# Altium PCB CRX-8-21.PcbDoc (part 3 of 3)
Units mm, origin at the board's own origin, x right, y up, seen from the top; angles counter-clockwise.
Board outline 160.02 x 101.6 mm, 2 copper layers (TopLayer, BottomLayer), stack 1.535 mm thick; 254 components, 127 nets, 595 pads, 4322 vias.
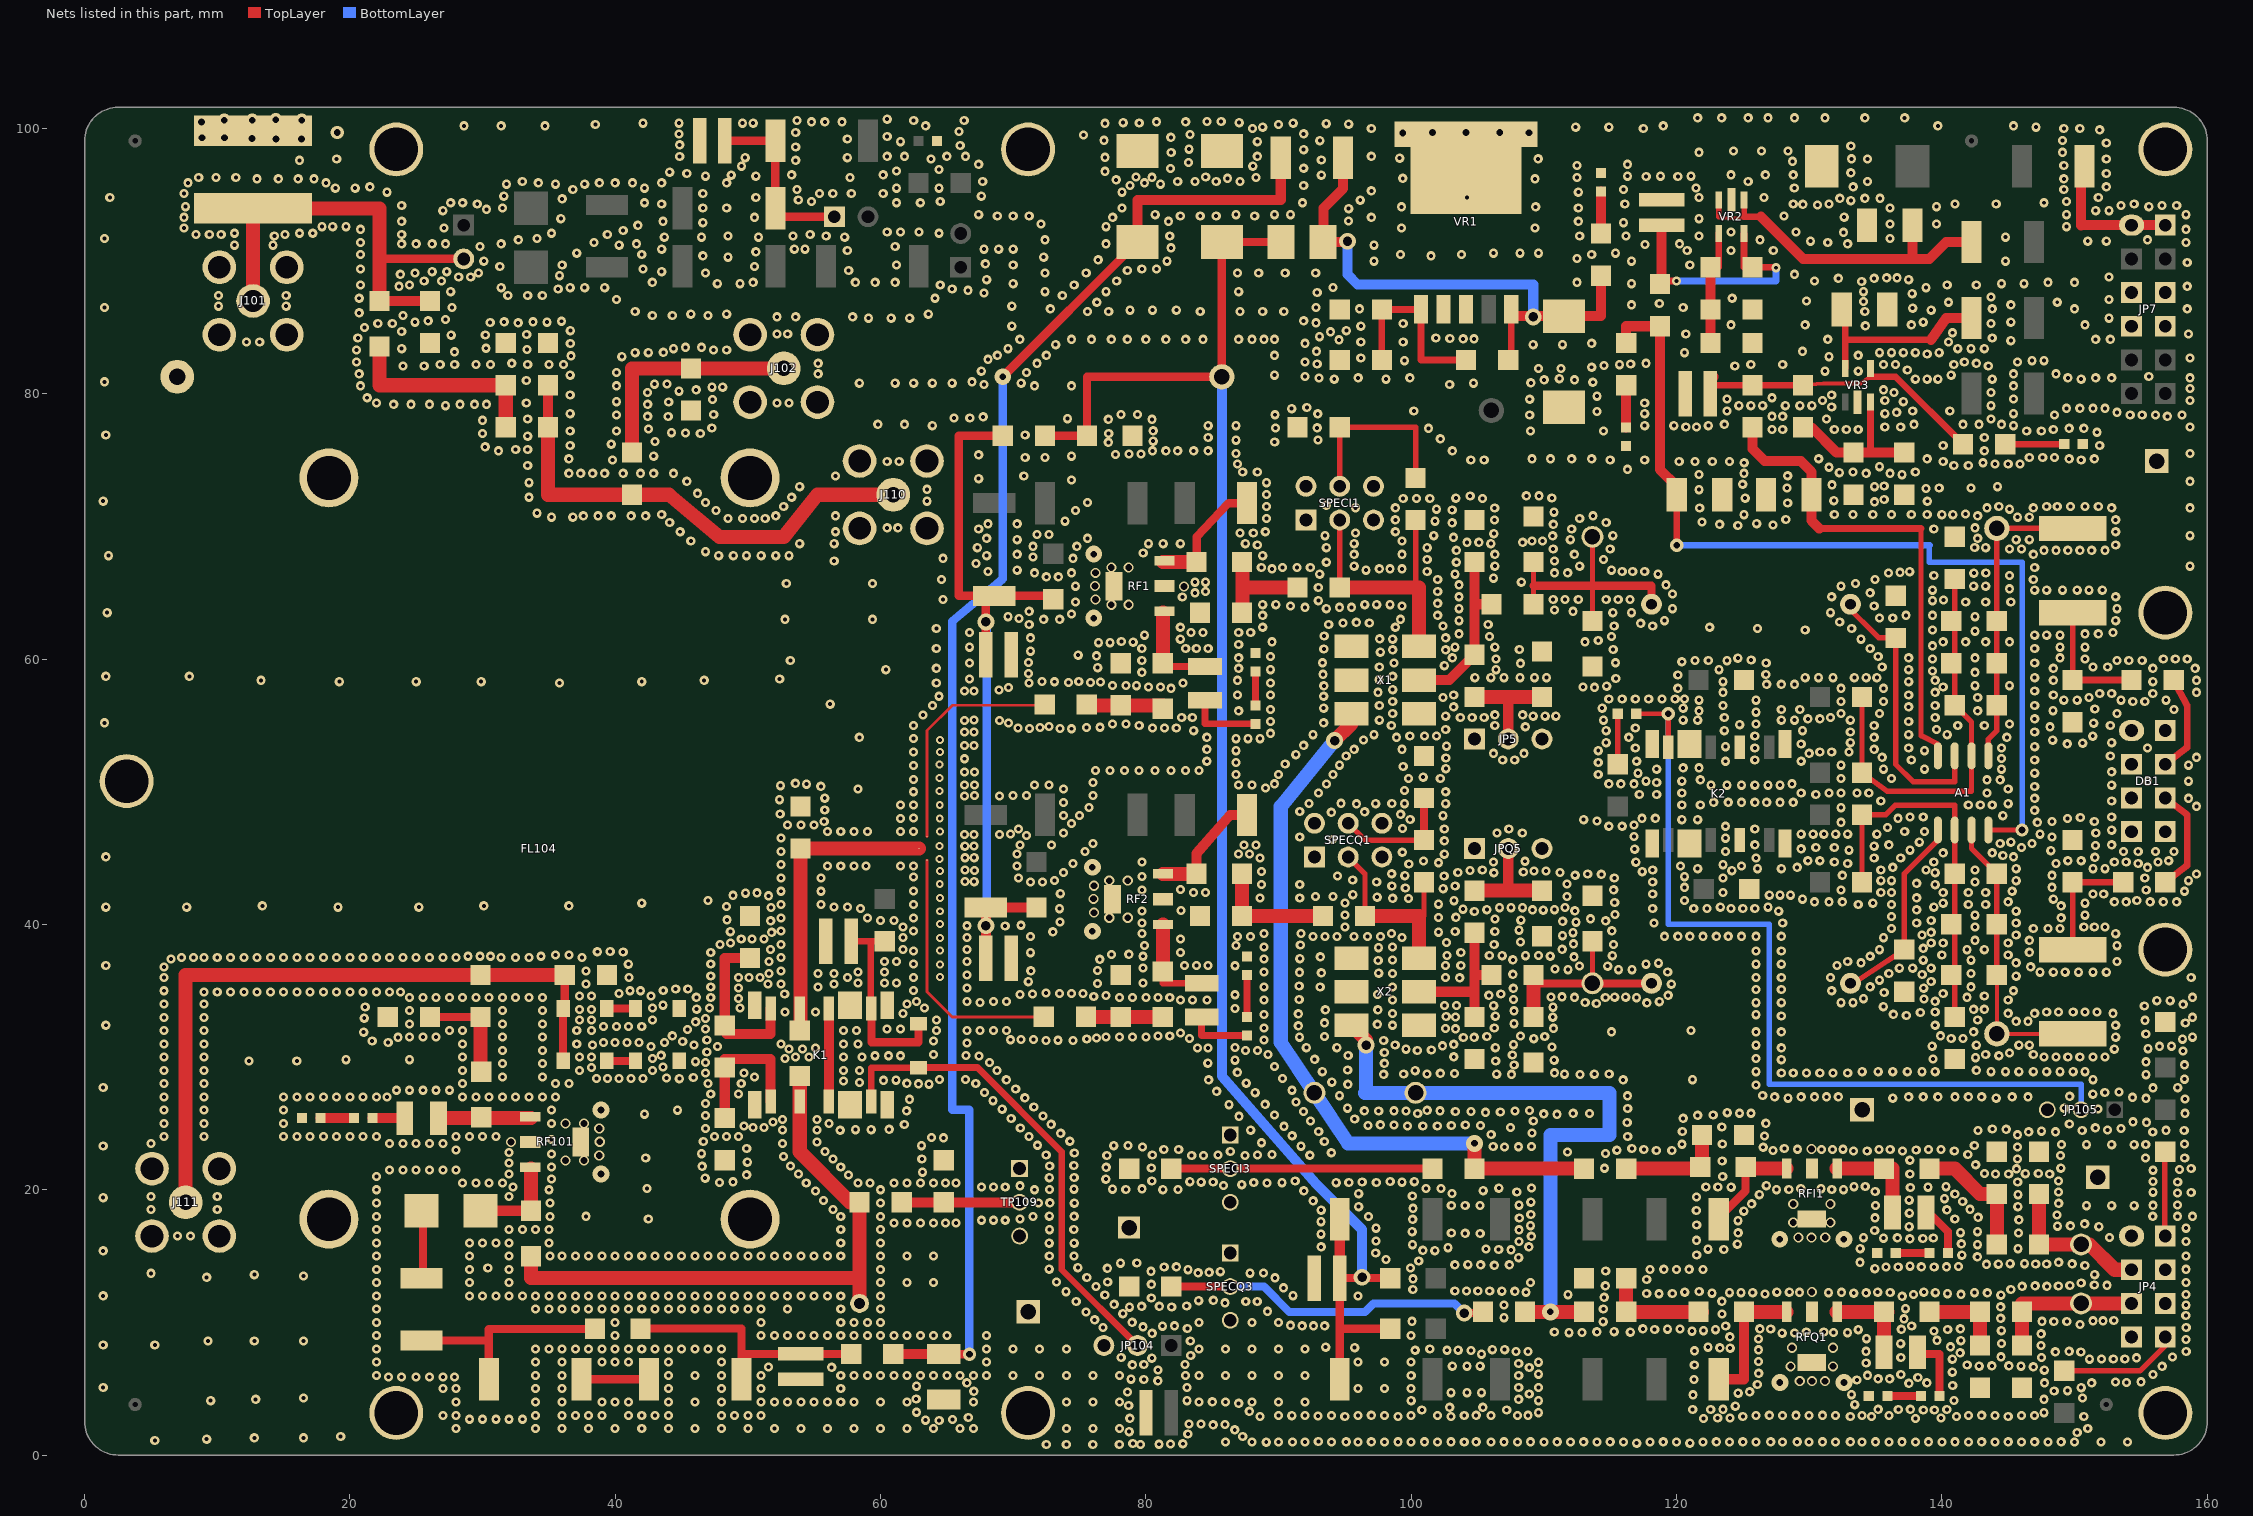
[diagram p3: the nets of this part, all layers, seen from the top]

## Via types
v1: diameter 0.7, hole 0.3, TopLayer to BottomLayer, 3209 vias
v2: diameter 0.68, hole 0.3, TopLayer to BottomLayer, 1006 vias
v3: diameter 0.762, hole 0.508, TopLayer to BottomLayer, 39 vias
v4: diameter 1, hole 0.508, TopLayer to BottomLayer, 20 vias
v5: diameter 1.27, hole 0.508, TopLayer to BottomLayer, 19 vias
v6: diameter 0.6, hole 0.3, TopLayer to BottomLayer, 19 vias
v7: diameter 1.27, hole 0.711, TopLayer to BottomLayer, 10 vias

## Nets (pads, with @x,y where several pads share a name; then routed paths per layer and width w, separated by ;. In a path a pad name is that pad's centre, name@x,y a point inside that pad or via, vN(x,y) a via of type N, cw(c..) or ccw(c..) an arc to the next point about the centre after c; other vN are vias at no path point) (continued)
GND: (continued)
  other v6: 64.489,36.035 64.486,36.996 64.489,38.048 64.489,38.992 64.486,40.034 64.476,40.993 64.466,41.998 64.463,43.038 64.466,44.037 64.461,44.937 64.458,45.895 64.471,47 64.463,47.986 64.463,49.01 64.458,50.044 64.461,51.03 64.461,52.042 64.474,53.007 64.468,53.895
K2-RELAY: JP105.2 K2.8 LED4.2 | length 66
  TopLayer w0.305: LED4.2@116.84,55.88 LED4.2@116.967,55.88 v4(119.38,55.88)
  TopLayer w0.406: K2.8@119.38,53.34 K2.8@119.38,53.355 v4(119.38,55.88)
  BottomLayer w0.406: v4(119.38,55.88) 119.38,40.005 127,40.005 127,27.94 150.495,27.94 JP105.2@150.495,26.035
LF4: C40.1 JP5.2 R40.2 | length 8.3
  TopLayer w0.762: JP5.2@107.315,53.975 107.315,57.15
  TopLayer w1.064: R40.2@104.775,57.15 107.315,57.15 C40.1@109.855,57.15
LFI1: R20.1 R21.1 R40.1 X1.2 | length 13.2
  TopLayer w0.762: X1.2@100.584,58.42 102.87,58.42 R40.1@104.775,60.325 104.775,64.135 ; R20.1@104.775,67.31 104.775,64.135 ; R21.1@106.045,64.135 104.775,64.135
LFI2: C20.1 C21.1 C22.1 R21.2 TP14.TP | length 19.8
  TopLayer w0.406: R21.2@109.22,64.135 109.22,65.532 C20.1@109.22,67.31 ; C21.1@113.665,62.865 113.665,65.532 TP14.TP@113.665,69.215
  TopLayer w0.61: 109.22,65.532 113.665,65.532 118.11,65.532 C22.1@118.11,64.135
LFI3: A1.3 C22.2 R22.1 | length 21.4
  TopLayer w0.406: C22.2@132.715,64.135 135.255,61.595 R22.1@136.525,61.595 136.525,52.07 137.836,50.759 140.97,50.759 A1.3@140.97,52.705 A1.3@140.97,52.832
LFQ1: RQ20.1 RQ21.1 RQ40.1 X2.2 | length 11.8
  TopLayer w0.762: X2.2@100.584,34.925 104.775,34.925 ; RQ20.1@104.775,33.02 104.775,34.925 ; RQ40.1@104.775,39.37 104.775,36.195 ; RQ21.1@106.045,36.195 104.775,36.195 ; 104.775,34.925 104.775,36.195
LFQ2: CQ20.1 CQ21.1 CQ22.1 RQ21.2 TPQ14.TP | length 15.2
  TopLayer w0.406: TPQ14.TP@113.665,35.56 CQ21.1@113.665,38.735
  TopLayer w0.61: RQ21.2@109.22,35.56 TPQ14.TP@113.665,35.56 CQ22.1@118.11,35.56
  TopLayer w1.064: CQ20.1@109.22,33.02 109.22,35.56 RQ21.2@109.22,36.195
LFQ3: A1.5 CQ22.2 RQ22.1 | length 14.5
  TopLayer w0.406: CQ22.2@133.35,35.56 RQ22.1@137.16,38.1 137.16,43.815 139.7,46.355 A1.5@139.7,46.99
LFQ4: CQ40.1 JPQ5.2 RQ40.2 | length 7.6
  TopLayer w0.762: 107.315,42.545 JPQ5.2@107.315,45.72
  TopLayer w1.064: RQ40.2@104.775,42.545 107.315,42.545 CQ40.1@109.22,42.545
LNA1: C100.1 GAP1.1 J101.1 JP102.2 R110.1 | length 33.7
  TopLayer w0.635: 22.225,90.17 JP102.2@28.575,90.17
  TopLayer w0.762: C100.1@22.225,86.995 R110.1@26.035,86.995
  TopLayer w1.064: J101.1@12.7,86.995 GAP1.1@12.7,93.98 22.225,93.98 22.225,90.17 C100.1@22.225,86.995
LNA2: C100.2 R101.1 R103.1 | length 15.6
  TopLayer w1.064: C100.2@22.225,83.566 22.225,80.645 R101.1@31.75,80.645 R103.1@31.75,77.47
LNA3: J110.1 R102.2 R103.2 R210.2 | length 37
  TopLayer w0.762: R103.2@34.925,77.47 R102.2@34.925,80.645
  TopLayer w1.064: R103.2@34.925,77.47 34.925,72.39 R210.2@41.275,72.39 44.052,72.39 47.862,69.215 52.705,69.215 55.245,72.39 J110.1@60.96,72.39
LNA4: D101.CATH D103.ANOD J111.1 R104.1 R105.1 | length 52.2
  TopLayer w0.61: D103.ANOD@36.068,29.591 D103.ANOD@36.068,29.718 D101.CATH@36.068,33.655 ; D101.CATH@36.195,33.782 R104.1@36.195,36.195
  TopLayer w1.064: J111.1@7.62,19.05 7.62,36.195 R105.1@29.845,36.195 R104.1@36.195,36.195
LNA5: C101.1 R105.2 R106.1 | length 7.6
  TopLayer w0.635: R106.1@26.035,33.02 R105.2@29.845,33.02
  TopLayer w1.064: C101.1@29.845,29.21 R105.2@29.845,33.02
LNA6: C101.2 L50.2 RF101.1 | length 7
  TopLayer w1.064: L50.2@26.67,25.4 RF101.1@33.655,25.4
LNA7: C102.1 L104.1 RF101.3 | length 7
  TopLayer w0.762: L104.1@29.845,18.415 C102.1@33.655,18.415
  TopLayer w1.064: C102.1@33.655,18.415 RF101.3@33.655,21.59
LNA8: C102.2 K1.6 R111.1 R208.1 TP108.TP | length 47
  TopLayer w1.064: C102.2@33.655,14.9 33.655,13.335 58.42,13.335 ; R208.1@53.909,28.575 53.909,26.035 K1.6@53.909,26.655 53.909,22.86 57.719,19.05 R111.1@58.42,19.05 58.42,13.335 ; TP108.TP@58.42,11.43 58.42,13.335
LNA9: K1.5 R204.1 R205.1 | length 11.1
  TopLayer w0.762: R204.1@48.26,25.4 R205.1@48.26,29.21 48.26,29.845 51.709,29.845 K1.5@51.709,26.655
LNA10: K1.4 R205.2 R206.1 | length 13.1
  TopLayer w0.762: R205.2@48.26,32.131 R205.2@48.26,32.385 ; R206.1@50.165,37.465 48.26,37.465 R205.2@48.26,32.385 ; K1.4@51.714,33.655 51.709,31.75 48.387,31.75 R205.2@48.26,32.385
LNA11: K1.2 K1.7 | length 7
  TopLayer w0.762: K1.7@56.109,26.655 K1.2@56.109,33.64
LNA13: R111.2 R112.1 TP109.2 | length 8.9
  TopLayer w0.762: R111.2@61.595,19.05 R112.1@64.77,19.05 TP109.2@70.485,19.05
LOI1: JP4.3 R10.2 R11.1 TP2.TP | length 11.6
  TopLayer w1.064: R10.2@147.32,19.685 R11.1@147.32,15.875 TP2.TP@150.495,15.875 151.13,15.875 153.035,13.97 JP4.3@154.305,13.97
LOI2: C4.1 R11.2 R12.2 | length 9.7
  TopLayer w1.064: C4.1@139.065,21.59 140.97,21.59 142.875,19.685 R12.2@144.145,19.685 R11.2@144.145,15.875
LOI3: C4.2 L53.1 RFI1.1 | length 7.5
  TopLayer w1.064: RFI1.1@132.08,21.59 C4.2@135.636,21.59 136.271,21.59 L53.1@136.271,18.288
LOI4: C5.2 L3.1 RFI1.3 | length 7.7
  TopLayer w0.61: L3.1@123.19,17.78 123.19,17.907 125.2,19.917 C5.2@125.2,21.59
  TopLayer w1.064: C5.2@125.2,21.59 RFI1.3@128.27,21.59
LOI5: C5.1 R16.1 R17.1 | length 8.3
  TopLayer w1.064: R16.1@116.205,21.59 121.92,21.59 R17.1@121.92,24.13
LOI6: R16.2 R18.1 TP5.TP X1.6 | length 55.6
  TopLayer w1.064: v7(94.23,53.857) 95.504,55.131 X1.6@95.504,55.88 ; v5(104.775,23.495) R18.1@104.775,21.59 R16.2@113.03,21.59
  BottomLayer w1.064: v7(94.23,53.857) 90.17,48.895 90.17,31.115 TP5.TP@92.71,27.305 95.25,23.495 v5(104.775,23.495)
LOQ1: JP4.5 RQ10.2 RQ11.1 TP1.TP | length 11.4
  TopLayer w1.064: RQ10.2@146.05,8.255 RQ11.1@146.05,10.795 146.05,11.43 TP1.TP@150.495,11.43 JP4.5@154.305,11.43
LOQ2: CQ4.1 RQ11.2 RQ12.2 | length 6.3
  TopLayer w1.064: CQ4.1@139.065,10.795 RQ11.2@142.875,10.795 RQ12.2@142.875,8.255
LOQ3: CQ4.2 L54.1 RFQ1.1 | length 6.9
  TopLayer w1.064: RFQ1.1@132.08,10.795 CQ4.2@135.636,10.795 ; L54.1@135.636,7.747 CQ4.2@135.636,10.795 ; CQ4.2@135.89,10.795 CQ4.2@135.636,10.795
LOQ4: CQ5.1 LQ3.1 RFQ1.3 | length 10.2
  TopLayer w0.762: LQ3.1@123.19,5.715 125.095,5.715 CQ5.1@125.095,10.795
  TopLayer w1.064: CQ5.1@125.095,10.795 RFQ1.3@128.27,10.795
LOQ5: CQ5.2 RQ16.1 RQ17.1 | length 8.3
  TopLayer w1.064: RQ17.1@116.205,13.335 RQ16.1@116.205,10.795 CQ5.2@121.666,10.795 CQ5.2@121.92,10.795
LOQ6: RQ16.2 RQ18.1 TPQ5.TP X2.6 | length 49.4
  TopLayer w1.064: X2.6@95.504,32.385 96.6,31.289 v7(96.6,30.9) ; RQ18.1@108.585,10.795 v5(110.49,10.795) RQ16.2@113.03,10.795
  BottomLayer w1.064: v7(96.6,30.9) 96.6,27.385 96.52,27.305 TPQ5.TP@100.33,27.305 114.935,27.305 114.935,24.13 110.49,24.13 v5(110.49,10.795)
MMIC_BUS: JP7.1 JP7.2 L1.2 | length 10.8
  TopLayer w0.762: L1.2@150.5,97.145 150.5,92.7 154.305,92.708 155.3,92.71 JP7.2@156.845,92.71
N43121: A1.6 CQ25.2 CQ26.2 RQ25.2 RQ26.1 RQ27.1 RQ28.1 | length 28.3
  TopLayer w0.406: RQ28.1@133.985,43.18 RQ27.1@133.985,48.26 135.763,48.26 136.48,48.977 140.97,48.977 A1.6@140.97,47.117 RQ25.2@140.97,43.815 RQ26.1@140.97,33.02
N78610: R30.2 R31.1 R32.1 VR1.1 | length 14.2
  TopLayer w0.508: R32.1@97.79,82.55 R31.1@97.79,86.36 VR1.1@100.736,86.36 ; VR1.1@100.965,86.36 VR1.1@100.736,86.36 ; R30.2@104.14,82.55 100.736,82.55 VR1.1@100.736,86.36
N571744: A1.2 C25.2 C26.2 R25.2 R26.1 R27.1 R28.1 | length 31
  TopLayer w0.406: R28.1@133.985,57.15 R27.1@133.985,51.435 135.89,50.038 142.24,50.038 A1.2@142.24,52.705 142.24,55.245 R25.2@140.97,56.515 R26.1@140.97,66.04
N3983590: LED1.1 R53.2 | length 3.2
  TopLayer w0.762: R53.2@114.3,92.075 LED1.1@114.3,95.25
N11845427: J102.1 R209.1 R210.1 | length 17.8
  TopLayer w0.61: R209.1@45.72,81.915 R209.1@45.815,81.915
  TopLayer w1.064: R210.1@41.275,75.565 41.275,81.915 R209.1@45.72,81.915 ; R209.1@45.8,81.9 45.815,81.915 J102.1@52.705,81.915
N11893488: JP4.2 L10.1 | length 6.3
  TopLayer w0.406: JP4.2@156.8,16.55 L10.1@156.8,22.9
N11893519: JP4.8 L107.1 | length 9
  TopLayer w0.406: L107.1@149.225,6.35 154.94,6.35 156.845,8.255 JP4.8@156.845,8.89
N114271571: D103.CATH D104.ANOD | length 2
  TopLayer w0.61: D103.CATH@39.37,29.718 D104.ANOD@41.402,29.718
N114277610: D101.ANOD D102.CATH | length 2.2
  TopLayer w0.61: D101.ANOD@39.37,33.655 D102.CATH@41.529,33.655
N117251600: C53.1 R73.1 | length 2.5
  TopLayer w0.61: C53.1@136.525,15.24 R73.1@139.065,15.24
N117251601: L53.2 R73.2 | length 3.8
  TopLayer w0.61: L53.2@138.811,18.288 139.414,17.886 140.462,16.838 R73.2@140.462,15.24
N117251820: C51.1 R71.1 | length 2.5
  TopLayer w0.508: R71.1@88.265,56.515 C51.1@88.265,59.055
N117251821: L51.1 R71.2 | length 5.6
  TopLayer w0.508: L51.1@84.455,56.896 84.455,55.118 R71.2@88.265,55.118
N117252040: C52.1 R72.1 | length 3
  TopLayer w0.508: R72.1@87.63,33.02 C52.1@87.63,36.068
N117252041: L52.1 R72.2 | length 4.8
  TopLayer w0.508: L52.1@84.201,33.02 84.201,31.623 R72.2@87.63,31.623
N117252260: C54.1 R74.1 | length 2.5
  TopLayer w0.61: C54.1@135.89,4.445 R74.1@138.43,4.445
N117252261: L54.2 R74.2 | length 4.6
  TopLayer w0.61: L54.2@138.43,7.62 139.827,7.62 R74.2@139.827,4.445
N117311520: C50.1 R70.1 | length 2.5
  TopLayer w0.762: C50.1@17.78,25.4 R70.1@20.32,25.4
N117311521: L50.1 R70.2 | length 2.4
  TopLayer w0.762: R70.2@21.717,25.4 L50.1@24.13,25.4
N119030500: LED4.1 R54.1 | length 3.8
  TopLayer w0.406: R54.1@115.57,52.07 LED4.1@115.57,55.88
OUTI1: A1.1 C25.1 C26.1 C27.1 R25.1 TP3.TP | length 23.1
  TopLayer w0.406: A1.1@143.51,52.705 143.51,53.975 144.145,54.61 R25.1@144.145,56.515 C25.1@144.145,59.69 C26.1@144.145,62.865 TP3.TP@144.145,69.85 C27.1@149.86,69.85
OUTI2: C27.2 R29.1 R50.1 | length 9.5
  TopLayer w0.406: R29.1@149.86,58.42 C27.2@149.86,63.5
  TopLayer w0.508: R29.1@149.86,58.42 R50.1@154.305,58.42
OUTI3: DB1.4 R50.2 | length 7.4
  TopLayer w0.508: DB1.4@156.845,52.07 158.496,53.34 158.496,56.515 R50.2@157.48,58.42
OUTQ1: A1.7 CQ25.1 CQ26.1 CQ27.1 RQ25.1 TPQ3.TP | length 21.9
  TopLayer w0.305: CQ26.1@144.145,36.195 TPQ3.TP@144.145,31.75 CQ27.1@149.86,31.75
  TopLayer w0.406: A1.7@142.24,47.117 142.24,45.72 RQ25.1@144.145,43.815 CQ25.1@144.145,40.005 CQ26.1@144.145,36.195
OUTQ2: CQ27.2 RQ29.1 RQ50.1 | length 8.9
  TopLayer w0.406: CQ27.2@149.86,38.1 RQ29.1@149.86,43.18
  TopLayer w0.508: RQ29.1@149.86,43.18 RQ50.1@153.67,43.18
OUTQ3: DB1.6 RQ50.2 | length 8
  TopLayer w0.508: RQ50.2@156.845,43.18 158.496,44.45 158.496,48.26 DB1.6@156.845,49.53
RELAY1: C108.1 D105.CATH K1.1 R207.2 | length 15.4
  TopLayer w0.508: C108.1@57.785,38.735 59.259,38.735 ; K1.1@59.259,33.655 59.259,38.735 ; R207.2@60.325,38.735 60.325,38.5 60.09,38.735 59.259,38.735
  TopLayer w0.61: K1.1@59.309,33.655 59.309,31.115 62.865,31.115 D105.CATH@62.865,32.512
RELAY2: D105.ANOD JP104.2 K1.8 | length 36.5
  TopLayer w0.508: K1.8@59.3,26.645 59.3,29.2 62.855,29.2 D105.ANOD@62.865,29.21 67.31,29.21 73.66,22.86 73.66,13.97 JP104.2@79.375,8.255
RF: ?.2 ?.3 R1.1 R2.1 | length 37.2
  TopLayer w0.2: 63.496,34.929 ?.3@63.496,44.827 ; ?.2@63.496,46.627 63.496,54.606 ; 63.5,34.925 65.405,33.02 R2.1@72.308,33.02 ; 63.5,54.61 65.405,56.515 R1.1@72.433,56.515
RF1: ?.1 K1.3 R7.1 R208.2 | length 22.5
  TopLayer w1.064: R208.2@53.975,32.068 R7.1@53.975,45.72 ; R7.1@54.101,45.718 54.11,45.727 ?.1@62.896,45.727
RFI2: C1.2 R1.2 R3.1 | length 5.5
  TopLayer w1.064: R1.2@75.739,56.515 R3.1@78.105,56.515 C1.2@81.28,56.515
rfi2x: 
RFI3: C1.1 L51.2 RF1.1 | length 7
  TopLayer w0.508: C1.1@81.28,59.436 L51.2@84.455,59.436
  TopLayer w1.064: C1.1@81.28,59.69 RF1.1@81.28,63.5
RFI4: C2.1 L4.1 RF1.3 | length 9.3
  TopLayer w0.635: C2.1@83.82,67.31 83.82,69.215 86.233,71.755 L4.1@87.63,71.755
  TopLayer w1.064: RF1.3@81.28,67.31 C2.1@83.82,67.31
RFI5: C2.2 R60.2 R61.1 | length 8
  TopLayer w1.064: R60.2@87.295,63.5 87.295,65.405 ; C2.2@87.295,67.31 87.295,65.405 ; R61.1@91.44,65.405 87.295,65.405
RFI6: R61.2 R63.2 SPECI1.3 X1.3 | length 20.8
  TopLayer w0.406: R61.2@94.615,65.405 SPECI1.3@94.615,70.485 ; 100.33,65.405 R63.2@100.33,70.485
  TopLayer w1.064: R61.2@94.615,65.405 100.33,65.405 100.584,65.405 X1.3@100.584,60.96 X1.3@100.33,60.96
RFQ2: CQ1.2 R2.2 R4.1 | length 5.7
  TopLayer w0.406: CQ1.2@81.28,33.02 CQ1.2@81.28,33.274
  TopLayer w1.064: R2.2@75.801,33.02 R4.1@78.105,33.02 CQ1.2@81.28,33.02
RFQ3: CQ1.1 L52.2 RF2.1 | length 7.4
  TopLayer w0.508: CQ1.1@81.28,36.195 81.28,35.56 L52.2@84.201,35.56
  TopLayer w1.064: CQ1.1@81.28,36.195 CQ1.1@81.28,36.449 RF2.1@81.28,40.005
RFQ4: CQ2.1 LQ4.1 RF2.3 | length 9.2
  TopLayer w0.762: CQ2.1@83.82,43.815 83.82,45.339 86.36,48.26 LQ4.1@87.63,48.26
  TopLayer w1.064: RF2.3@81.28,43.815 CQ2.1@83.82,43.815
RFQ5: CQ2.2 RQ60.2 RQ61.1 | length 9.3
  TopLayer w1.064: CQ2.2@87.249,43.815 RQ60.2@87.249,40.64 RQ61.1@93.345,40.64
RFQ6: RQ61.2 RQ63.2 SPECQ1.3 X2.3 | length 15.4
  TopLayer w0.406: SPECQ1.3@95.25,45.085 96.52,43.815 RQ61.2@96.52,40.64 ; 100.584,40.64 100.965,40.64 RQ63.2@100.965,43.18
  TopLayer w1.064: RQ61.2@96.52,40.64 100.584,40.64 X2.3@100.584,37.465 X2.3@100.33,37.465
SPEC-I: R63.1 R64.2 SPECI1.4 | length 14
  TopLayer w0.406: SPECI1.4@94.615,73.025 R64.2@94.615,77.47 100.33,77.47 R63.1@100.33,73.66
SPEC-Q: RQ63.1 RQ64.2 SPECQ1.4 | length 9.4
  TopLayer w0.406: SPECQ1.4@95.25,47.625 96.52,46.355 RQ63.1@100.965,46.355
  TopLayer w0.61: RQ63.1@100.965,46.355 RQ64.2@100.965,49.53
TP-I2: R18.2 R19.2 SPECI3.2 | length 19.7
  TopLayer w0.61: R19.2@81.915,21.59 SPECI3.2@86.36,21.59 R18.2@101.6,21.59
TP-Q1: RQ18.2 RQ19.2 SPECQ3.2 | length 24.9
  TopLayer w0.61: RQ19.2@81.915,12.7 SPECQ3.2@86.36,12.7 ; v7(104,10.7) 105.315,10.7 RQ18.2@105.41,10.795
  BottomLayer w0.61: SPECQ3.2@86.36,12.7 88.9,12.7 90.805,10.795 96.52,10.795 97.155,11.43 103.27,11.43 v7(104,10.7)
VC10: C6.1 C7.1 R6.1 R37.1 R92.2 R93.1 RQ6.1 | length 57.5
  TopLayer w0.635: C7.1@67.945,60.325 v7(67.945,62.8) R6.1@67.945,64.77 ; R37.1@69.215,76.835 65.885,76.835 65.885,64.77 R6.1@67.945,64.77 ; R92.2@73.025,64.77 R6.1@68.58,64.77 R6.1@67.945,64.77
  TopLayer w0.762: C6.1@67.945,37.465 v7(67.945,39.9) RQ6.1@67.945,41.275 R93.1@71.755,41.275
  BottomLayer w0.635: v7@68,39.8 v7@68,62.66
VC14: C107.1 JP103.1 R116.1 R120.2 | length 13.6
  TopLayer w0.635: C107.1@48.26,99.06 R116.1@52.07,99.06 R120.2@52.07,93.98 52.705,93.345 JP103.1@56.515,93.345
VCC: C33.1 C34.1 CQ7.1 L2.1 R13.1 R37.2 R91.1 R94.1 RQ13.1 TP9.TP | length 124.1
  TopLayer w0.61: RQ13.1@94.615,5.715 94.615,9.525 CQ7.1@94.615,13.335 R91.1@98.425,13.335
  TopLayer w0.635: R37.2@72.39,76.835 C34.1@75.565,76.835 75.565,81.28 TP9.TP@85.725,81.28 C33.1@85.725,91.44 L2.1@90.17,91.44 ; 94.615,9.525 R94.1@98.425,9.525
  TopLayer w0.762: CQ7.1@94.615,13.335 R13.1@94.615,17.78
  BottomLayer w0.762: TP9.TP@85.725,81.28 85.725,28.575 92.844,20.439 96.3,16.983 v7(96.3,13.4)
VDD: A1.8 C23.1 R23.1 R51.2 | length 70.9
  TopLayer w0.406: A1.8@143.51,47.117 v4(146.05,47.117)
  TopLayer w0.508: v4(120.015,68.58) C23.1@120.015,72.39
  TopLayer w0.762: R51.2@116.205,83.82 116.205,85.09 R23.1@118.745,85.09 118.745,74.295 120.015,73.025 C23.1@120.015,72.39
  BottomLayer w0.406: 139.065,68.58 139.065,67.31 146.05,67.31 v4(146.05,47.117)
  BottomLayer w0.508: v4(120.015,68.58) 139.065,68.58
VEE: A1.4 CQ24.1 RQ24.2 | length 36.9
  TopLayer w0.406: 138.43,69.85 138.43,54.229 139.7,53.594 A1.4@139.7,52.705
  TopLayer w0.508: 130.762,69.85 138.43,69.85
  TopLayer w0.762: RQ24.2@125.73,77.47 125.73,75.852 126.652,74.93 129.363,74.93 130.175,74.118 CQ24.1@130.175,72.39 130.175,70.437 130.762,69.85
VLNA1: C104.1 C105.1 L106.1 R107.1 | length 114
  TopLayer w0.635: C105.1@64.77,7.62 64.79,7.6 v4(66.7,7.6) ; v5(69.215,81.28) C104.1@79.375,91.44
  TopLayer w0.762: R107.1@60.96,7.62 C105.1@64.77,7.62 ; C104.1@79.375,91.44 79.375,94.615 90.17,94.615 L106.1@90.17,97.79
  BottomLayer w0.635: v4(66.7,7.6) 66.675,7.625 66.675,26.035 65.405,26.035 65.405,62.865 69.215,66.04 v5(69.215,81.28)
VLNA2: C106.1 R90.1 R107.2 R108.2 | length 19.7
  TopLayer w0.61: R90.1@41.91,9.525 49.53,9.525 49.53,7.62 ; R108.2@49.53,5.715 49.53,7.62 ; R107.2@57.785,7.62 C106.1@53.975,7.62 49.53,7.62
VLNA3: R108.1 R109.2 | length 5.1
  TopLayer w0.61: R109.2@37.465,5.715 R108.1@42.545,5.715
VLNA4: L103.2 R90.2 R109.1 | length 16.9
  TopLayer w0.61: L103.2@25.4,8.636 30.48,8.636
  TopLayer w0.635: R109.1@30.48,5.715 30.48,8.636 30.48,9.48 30.5,9.5 38.456,9.5 R90.2@38.481,9.525
VLNA5: L103.1 L104.2 | length 5.1
  TopLayer w0.61: L103.1@25.5,13.32 L104.2@25.5,18.4
VR+1: C39.1 L8.1 VR2.1 VR2.3 | length 26
  TopLayer w0.254: 123.19,93.345 123.325,93.255 124.915,93.255 125.095,93.345
  TopLayer w0.406: 123.19,93.345 VR2.3@123.19,94.615 ; 125.095,93.345 VR2.1@125.095,94.615
  TopLayer w0.508: 125.095,93.345 126.365,93.345
  TopLayer w0.762: 126.365,93.345 129.54,90.17 137.795,90.17 ; C39.1@137.795,92.71 137.795,90.17 ; L8.1@142.24,91.44 140.335,91.44 139.065,90.17 137.795,90.17
VR+2: R41.2 R42.1 R422.1 VR2.4 | length 8.9
  TopLayer w0.508: R41.2@122.555,89.535 123.19,89.535 VR2.4@123.19,92.075
  TopLayer w0.762: R422.1@122.555,83.82 R42.1@122.555,86.36 R41.2@122.555,89.535
VR+3: C37.1 R23.2 R41.1 VR2.5 | length 19.3
  TopLayer w0.508: R23.2@118.745,88.5 118.872,88.5 v2(120,88.5) ; VR2.5@125.095,92.075 125.095,89.535 R41.1@125.73,89.535 127.465,89.535 v2(127.5,89.5)
  TopLayer w0.762: R23.2@118.745,88.265 118.872,88.265 118.872,88.5 C37.1@118.872,92.71
  BottomLayer w0.508: v2(120,88.5) 127.5,88.5 v2(127.5,89.5) v2@127.5,89.535
VR+4: LED2.1 R51.1 | length 3.2
  TopLayer w0.762: LED2.1@116.205,77.47 R51.1@116.205,80.645
VR-1: C30.2 L7.1 VR3.5 | length 15.1
  TopLayer w0.508: VR3.5@132.715,81.915 132.715,84.074 ; C30.2@132.715,86.36 132.715,84.074 ; 139.192,84.074 132.715,84.074
  TopLayer w0.762: C30.2@132.461,86.36 C30.2@132.715,86.36 ; 139.192,84.074 140.335,85.725 L7.1@142.24,85.725
VR-2: R43.2 R44.1 R442.1 VR3.3 | length 12.2
  TopLayer w0.508: 134.62,75.565 VR3.3@134.62,79.375
  TopLayer w0.762: R43.2@129.54,77.47 130.175,77.47 132.08,75.565 R44.1@133.35,75.565 134.62,75.565 R442.1@137.16,75.565
VR-3: C38.1 R43.1 R52.2 RQ24.1 VR3.4 | length 23.4
  TopLayer w0.305: R43.1@129.54,80.645 131.064,80.772 133.858,80.772 VR3.4@134.62,81.28
  TopLayer w0.508: C38.1@122.555,80.645 RQ24.1@125.73,80.645 R43.1@129.54,80.645 ; VR3.4@134.62,81.915 134.62,81.28 136.525,81.28 R52.2@141.605,76.2
  TopLayer w0.762: C38.1@122.555,80.01 C38.1@122.555,80.645 ; C38.1@122.555,80.772 C38.1@122.555,80.645 ; C38.1@122.784,81.28 C38.1@122.555,80.645
VR-4: LED3.2 R52.1 | length 4.4
  TopLayer w0.508: R52.1@144.78,76.2 LED3.2@149.225,76.2
VREG: C32.1 L2.2 L106.2 R30.1 R53.1 VR1.5 | length 42.4
  TopLayer w0.508: R30.1@107.544,82.55 VR1.5@107.544,86.36
  TopLayer w0.762: L2.2@93.345,91.44 L2.2@93.4,91.44 ; L106.2@94.869,97.79 94.869,95.469 93.4,94 L2.2@93.4,91.44 ; v7(95.2,91.5) 95.14,91.44 L2.2@93.4,91.44 ; R30.1@107.315,82.55 R30.1@107.544,82.55 ; VR1.5@107.544,86.36 107.569,85.852 C32.1@111.506,85.852 114.3,85.852 R53.1@114.3,88.9
  BottomLayer w0.762: v7(95.2,91.5) 95.2,89 95.956,88.244 108.8,88.244 109.2,88.247 v7@109.2,85.852
  other v7: 109.2,85.8
pads on no net: FID1.0 FID1.0_1 FID1.0_2 FID2.0 FID2.0_1 FID2.0_2 FID3.0 FID3.0_1 FID3.0_2 FID4.0 FID4.0_1 FID4.0_2 VR3.1

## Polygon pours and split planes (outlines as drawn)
GND on TopLayer "1" (solid, remove dead copper, pour order 2): 0.029,102.343 0.029,-0.01 160.049,-0.01 160.049,101.578
GND on BottomLayer "1" (solid, remove dead copper, pour order 4): 0,102.354 0,0 160.02,0 160.02,101.588

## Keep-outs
KeepOutLayer:
  lines w0.254: 153.035,101.6 154.305,101.6 ; 0,2.54 ccw(c2.54,2.54) 2.54,0 157.48,0 ccw(c157.48,2.54) 160.02,2.54 160.02,99.06 ccw(c157.48,99.06) 157.48,101.6 2.54,101.6 ccw(c2.54,99.06) 0,99.06 0,2.54

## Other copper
TopLayer:
  rectangle net GND: 154,60.3 159.2,66.6
  rectangle net GND: 68.5,96 73.4,100.7
  rectangle net GND: 47.4,71 52.7,76.3
  rectangle net GND: 20.32,0.635 26.035,5.715
  rectangle net GND: 7.62,99.06 19.685,100.33
  rectangle net GND: 15.24,14.605 21.59,21.59
  rectangle net GND: 0.635,48.26 5.715,53.34
  rectangle net GND: 98.425,92.075 109.855,97.79
  rectangle net GND: 11.43,97.155 13.97,99.695
  rectangle net GND: 153.67,34.29 159.385,40.64
  rectangle net GND: 15.24,71.12 22.225,76.835
  rectangle net GND: 45.72,15.24 53.34,20.955
  rectangle net GND: 20.32,95.885 27.305,100.965
  rectangle net GND: 67.945,0.635 73.66,6.35
  rectangle net GND: 7.397,98.248 18.163,101.2
  region net GND: 153.9,101 153.1,96.8 153.9,95.7 156.8,95.5 159.5,96.85 159.5,99.4 157.9,101
  region net GND: 157,7 154,4 154,2 155.5,0.5 158,0.5 159.5,2 159.5,6.5 159,7
BottomLayer:
  rectangle net GND: 154.1,60.3 159.2,66.4
  rectangle net GND: 68.5,96 73.4,100.7
  rectangle net GND: 47.4,71 52.7,76.3
  rectangle net GND: 20.32,0.635 26.035,5.715
  rectangle net GND: 68.58,0.635 73.66,5.715
  rectangle net GND: 0.635,47.625 5.715,53.975
  rectangle net GND: 15.24,15.24 20.955,20.955
  rectangle net GND: 20.955,95.885 26.035,100.965
  rectangle net GND: 154.305,35.56 159.385,40.64
  rectangle net GND: 46.99,15.24 52.705,20.32
  rectangle net GND: 15.5,71 22,76.5
  region net GND: 154,101.05 157.9,101.05 159.2,99.75 159.2,96.702 156.8,95.55 153.9,95.75 153.1,96.85
  region net GND: 157,7 154,4 154,2 155.5,0.5 158,0.5 159.5,2 159.5,6.5 159,7
MultiLayer:
  pour cut-out: 76.1,75 76.1,69.1 85.2,69.1 85.2,75
  pour cut-out: 111.2,20.6 111.2,14.7 120.9,14.7 120.9,20.6
  pour cut-out: 110.1,8.7 110.1,2.8 120.8,2.8 120.8,8.7
  pour cut-out: 22.9,20.9 22.9,6.3 28.4,6.3 28.6,6.1 28.6,3.2 33.6,3.2 33.6,10.8 28,10.8 27.9,10.7 27.9,20.8 28,20.9
  pour cut-out: 76.4,51.2 76.4,45.3 85.1,45.3 85.1,51.2

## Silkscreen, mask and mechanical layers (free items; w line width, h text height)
TopOverlay:
  rectangle: 10.795,1.27 20.955,6.35
  lines w0.203: 99.06,31.115 99.06,33.655 100.33,33.655 ; 99.06,54.61 99.06,57.15 100.965,57.15 ; 152.4,101.6 154.94,101.6
  lines w0.254: 153.035,101.6 154.305,101.6 ; 0,2.54 ccw(c2.54,2.54) 2.54,0 ; 0,2.54 ccw(c2.54,2.54) 2.54,0 ; 0,2.54 0,99.06 cw(c2.54,99.06) 2.54,101.6 157.48,101.6 cw(c157.48,99.06) 160.02,99.06 160.02,2.54 cw(c157.48,2.54) 157.48,0 2.54,0
  text "BIAS-T" at 26.67,98.425 h2.03
  text "Regulators" at 72.5,85 h2.03
  text "-20dBm" at 58.42,81.28 h1.52
  text "-24dB" at 89.535,76.835 h1.27 r270
  text "-5dB" at 89.535,70.485 h1.02 r270
  text "I" at 123.838,62.494 h3.05
  text "Radio Oceanography Laboratory" at 9.714,58.427 h1.52
  text "University of Hawaii SOEST" at 11.82,55.081 h1.52
  text "-24dB" at 89.826,52.07 h1.27 r270
  text "BASEBAND" at 103.886,49.276 h1.02
  text "-5dB" at 90.17,45.085 h1.02 r270
  text "Q" at 122.816,33.947 h3.05
  text "LNA" at 13.97,29.845 h2.54
  text "-20dB" at 83.439,28.067 h1.27
  text "ON  REMOTE" at 145.927,27.739 h1.02
  text "nom. -3dBm" at 89.535,25.4 h1.52 r270
  text "-10dB" at 67.564,25.273 h1.27
  text "CRX-8-21" at 1.27,9.525 h2.54
  text "Rev A" at 1.41,6.872 h1.52
  text "ON  REMOTE" at 74.93,5.715 h1.02
  text "S/N" at 5.715,2.54 h1.78
  text "Local Oscillator" at 111.252,0.508 h2.03
TopPaste:
  rectangle: 103.657,85.319 104.623,87.401
  rectangle: 101.956,85.319 102.921,87.376
BottomSolder:
  circle w0.762: c156.845,63.5 r2.54
  circle w0.762: c156.845,38.1 r2.54
  rectangle: 158.75,1.905 160.02,97.79
  lines w5.08: 157.48,2.54 149.225,2.54 88.9,2.54 2.54,2.54 2.54,99.06 157.48,99.06
Mechanical1:
  lines w0.203: 15.24,101.6 16.51,101.6 ; 15.393,103.045 15.875,101.6 16.357,103.045 ; 154.305,38.1 174.625,38.1 ; 154.94,63.5 174.625,63.5 ; 161.925,86.36 177.165,86.36 ; 162.56,12.7 167.64,12.7 ; 166.37,0 167.64,0 ; 166.523,1.445 167.005,0 ; 166.523,11.255 167.005,12.7 ; 167.005,2.729 167.005,0 ; 167.005,9.971 167.005,12.7 ; 167.487,1.445 167.005,0 ; 167.487,11.255 167.005,12.7 ; 168.91,101.6 175.26,101.6 ; 172.238,1.445 172.72,0 ; 172.238,49.355 172.72,50.8 ; 172.72,21.144 172.72,0 ; 172.72,29.656 172.72,50.8 ; 173.202,1.445 172.72,0 ; 173.202,49.355 172.72,50.8 ; 173.99,0 175.26,0 ; 174.143,-1.445 174.625,0 ; 174.143,36.655 174.625,38.1 ; 174.143,39.545 174.625,38.1 ; 174.143,62.055 174.625,63.5 ; 174.143,64.945 174.625,63.5 ; 174.143,103.045 174.625,101.6 ; 174.625,-1.905 174.625,0 ; 174.625,5.08 174.625,3.175 ; 174.625,16.487 174.625,3.175 ; 174.625,24.788 174.625,38.1 ; 174.625,46.65 174.625,38.1 ; 174.625,54.95 174.625,63.5 ; 174.625,76.812 174.625,63.5 ; 174.625,85.113 174.625,98.425 ; 174.625,96.52 174.625,98.425 ; 174.625,103.505 174.625,101.6 ; 175.107,-1.445 174.625,0 ; 175.107,36.655 174.625,38.1 ; 175.107,39.545 174.625,38.1 ; 175.107,62.055 174.625,63.5 ; 175.107,64.945 174.625,63.5 ; 175.107,103.045 174.625,101.6 ; 174.625,3.175 175.107,4.62 174.625,3.175 ; 174.625,3.175 174.143,4.62 174.625,3.175 ; 174.625,98.425 175.107,96.98 174.625,98.425 ; 174.625,98.425 174.143,96.98 174.625,98.425 ; 160.655,98.425 175.26,98.425 160.655,98.425 ; 162.56,50.8 173.355,50.8 162.56,50.8 ; 173.99,3.175 175.26,3.175 173.99,3.175 ; 173.99,38.1 175.26,38.1 173.99,38.1 ; 173.99,63.5 175.26,63.5 173.99,63.5
  lines w0.254: 160.02,0 165.735,0 ; 160.02,101.6 166.37,101.6 ; 177.8,86.36 179.07,86.36 ; 177.8,101.6 179.07,101.6 ; 177.953,87.805 178.435,86.36 ; 177.953,100.155 178.435,101.6 ; 178.435,90.359 178.435,86.36 ; 178.435,97.601 178.435,101.6 ; 178.917,87.805 178.435,86.36 ; 178.917,100.155 178.435,101.6
  lines w0.305: 154.305,61.595 156.845,63.5 ; 154.305,65.405 156.845,63.5 ; 156.464,63.5 156.845,63.5 ; 156.845,63.373 156.845,63.627 ; 160.02,63.373 160.02,63.627 ; 160.401,63.5 160.02,63.5 ; 162.56,61.595 160.02,63.5 ; 162.56,65.405 160.02,63.5
  text "125mil" at 169.545,99.06 h1.27
  text "600mil" at 177.713,97.347 h1.27 r270
  text "1375mil" at 173.903,84.859 h1.27 r270
  text "125mil" at 160.401,59.182 h1.52
  text "1000mil" at 173.903,54.696 h1.27 r270
  text "I" at 168.91,52.07 h4.06
  text "Q" at 168.402,45.72 h4.06
  text "2000mil" at 171.998,29.402 h1.27 r270
  text "1375mil" at 173.903,24.534 h1.27 r270
  text "I" at 168.656,13.97 h4.06
  text "500mil" at 166.283,9.717 h1.27 r270
  text "Q" at 168.148,7.62 h4.06
  text "125mil" at 174.625,1.27 h1.27
  text "L1812,L1210" at 114.935,-5.715 h1.02
Mechanical2:
  lines w0.254: -10.795,0 0,0 0,-5.08 ; -8.255,101.6 0,101.6 0,105.41 ; -0.635,50.8 0.635,50.8 ; 0,50.165 0,51.435 ; 2.54,50.8 3.81,50.8 ; 3.175,50.165 3.175,51.435 ; 160.02,-3.81 160.02,0 173.355,0 ; 160.02,101.6 160.02,104.14 ; 160.655,101.6 168.91,101.6
  lines w0.762: -3.81,-15.24 5.08,-15.24 ; 160.02,7.62 160.02,17.78
  text "QRX-8 PRODUCTION 2017" at -24.638,111.76 h10.16
  text "SPM FIXED" at -4.572,105.664 h2.03
  text "M-3.0 MOUNTING HOLES (3.3mm)" at 27.686,105.664 h4.44
  text "RX170316.pcb" at -21.59,104.14 h8.89 r270
  text "6300mil,4000mil" at 130.175,103.886 h2.03
  text "MOUNT M-3" at 18.415,102.235 h1.52
  text "MEXICO PROTOTYPE" at 182.88,100.965 h6.35 r270
  text "V12" at 167.894,91.821 h2.03
  text "+15V" at 166.624,89.281 h2.03
  text "GND" at 167.894,86.741 h2.03
  text "GND" at 167.894,84.201 h2.03
  text "-15V" at 166.624,81.661 h2.03
  text "Ant" at 167.894,79.121 h2.03
  text "fixed" at 19.685,78.74 h1.91
  text "BP-FILT-DW2" at -8.255,76.2 h4.44 r270
  text "GND" at 160.274,63.627 h2.03
  text "100 ohm" at 55.245,55.245 h1.02
  text "Fill with W=045" at 50.8,53.975 h1.02
  text "W=15, Gap= 25" at 50.8,52.705 h1.02
  text "GND" at 160.909,38.608 h2.03
  text "A-GAIN" at 161.29,18.415 h1.02
  text "ATTEN" at 161.29,6.35 h1.02
  text "150mil,150mil" at -11.938,2.159 h1.02
  text "GND" at 160.274,1.905 h2.03
  text "Poly Fill Gap 010" at 39.37,-1.905 h1.02
  text "HAS TENTED VIAS" at 88.9,-3.175 h1.52
  text "50 ohm" at 43.815,-3.81 h1.02
  text "Fill with W=050" at 39.37,-5.715 h1.02
  text "FOUR FIDUCIALS" at 56.515,-6.985 h1.52
  text "W=50, Gap= 10" at 39.37,-7.62 h1.02
  text "03/05/2017" at 5.715,-8.89 h2.54
  text "DRC 03/15/2017 RX170316.NET" at 97.155,-8.89 h2.54
  text "\__LERA-4p\__FABRICATION\BIDDING FILES on SERVER\QRX-8\20170305\" at -14.605,-12.7 h2.54
  text "RX170316.DSN" at 145.415,-12.7 h2.54
Mechanical3:
  lines w0.203: 36.83,23.495 38.1,23.495 ; 37.465,22.86 37.465,24.13
  text "-3500mil,1875mil" at 62.23,104.14 h1.52
  text "-5375mil,1875mil" at 15.24,103.505 h1.52
  text "-125mil,1875mil" at 156.845,101.6 h1.52
  text "-4325mil,900mil" at 38.1,76.835 h1.52
  text "-5575mil,900mil" at -5.08,73.025 h1.52
  text "-3900mil,850mil" at 48.895,66.675 h1.52
  text "-125mil,500mil" at 158.115,60.325 h1.52
  text "-6175mil,0mil" at -2.54,53.975 h1.52
  text "-6300mil,0mil" at -3.175,51.435 h1.52 r270
  text "-125mil,-500mil" at 158.115,34.925 h1.52
  text "-6000mil,-1250mil" at -2.54,30.48 h1.52 r270
  text "-4825mil,-1075mil" at 35.306,22.86 h1.52
  text "-5575mil,-1300mil" at 11.43,20.32 h1.52
  text "-4325mil,-1300mil" at 41.91,14.605 h1.52
  text "-5075mil,-1675mil" at 26.035,2.54 h1.52
  text "-4325mil,-1675mil" at 44.45,0.635 h1.52
  text "-5375mil,-1875mil" at 11.43,-1.905 h1.52
  text "-3500mil,-1875mil" at 60.325,-3.175 h1.52
  text "-1175mil,-1400mil" at 130.175,-3.81 h1.52
  text "-125mil,-1875mil" at 154.305,-3.81 h1.52
  text "-3250mil,575mil" at 72.39,-5.715 h1.52
  text "-1175mil,-1825mil" at 130.175,-5.715 h1.52
  text "-3250mil,-350mil" at 72.39,-8.89 h1.52
  text "-4825mil,-1075mil" at 33.02,-9.525 h1.52
Mechanical4:
  circle w0.254: c160.02,50.8 r2.54
  circle w0.254: c0,50.8 r1.27
  rectangle: 111.76,2.54 120.65,8.89
  rectangle: 111.76,15.24 120.65,20.32
  rectangle: 76.2,45.72 85.09,50.8
  rectangle: 76.2,69.215 85.09,74.295
  lines w0.203: 6.985,19.05 8.255,19.05 ; 7.62,18.415 7.62,19.685 ; 17.78,17.78 19.05,17.78 ; 18.415,17.145 18.415,18.415 ; 49.53,8.255 50.8,8.255 ; 49.53,17.78 50.8,17.78 ; 49.53,73.66 50.8,73.66 ; 50.165,7.62 50.165,8.89 ; 50.165,17.145 50.165,18.415 ; 50.165,73.025 50.165,74.295 ; 60.325,72.39 61.595,72.39 ; 60.96,71.755 60.96,73.025
  lines w0.254: -0.635,50.8 0.635,50.8 ; 0,50.165 0,51.435 ; 5.08,17.78 6.35,17.78 ; 5.715,17.145 5.715,18.415 ; 22.86,3.175 24.13,3.175 ; 23.495,2.54 23.495,3.81 ; 70.485,3.175 71.755,3.175 ; 70.485,98.425 71.755,98.425 ; 71.12,2.54 71.12,3.81 ; 71.12,97.79 71.12,99.06 ; 156.21,3.175 157.48,3.175 ; 156.21,5.715 ccw(c156.21,8.255) 158.75,8.255 158.75,33.02 ccw(c156.845,33.02) 156.845,34.925 cw(c156.845,38.1) 156.845,41.275 ccw(c156.845,43.18) 158.75,43.18 158.75,58.42 ccw(c156.845,58.42) 156.845,60.325 cw(c156.845,63.5) 156.845,66.675 ccw(c156.845,68.58) 158.75,68.58 158.75,93.345 ccw(c156.21,93.345) 156.21,95.885 ; 156.21,38.1 157.48,38.1 ; 156.21,63.5 157.48,63.5 ; 156.21,98.425 157.48,98.425 ; 156.845,2.54 156.845,3.81 ; 156.845,16.51 164.465,24.13 165.735,24.13 ; 156.845,37.465 156.845,38.735 ; 156.845,62.865 156.845,64.135 ; 156.845,97.79 156.845,99.06 ; 159.385,50.8 160.655,50.8 ; 160.02,50.165 160.02,51.435 ; 22.86,98.425 24.13,98.425 22.86,98.425 ; 23.495,97.79 23.495,99.06 23.495,97.79 ; 37.465,22.86 37.465,24.13 37.465,22.86 ; 76.835,41.91 78.105,41.91 76.835,41.91 ; 76.835,65.405 78.105,65.405 76.835,65.405 ; 77.47,41.275 77.47,42.545 77.47,41.275 ; 77.47,64.77 77.47,66.04 77.47,64.77 ; 129.54,6.985 130.81,6.985 129.54,6.985 ; 129.54,17.78 130.81,17.78 129.54,17.78 ; 130.175,6.35 130.175,7.62 130.175,6.35 ; 130.175,17.145 130.175,18.415 130.175,17.145
  text "0mil,0mil" at 160.655,50.8 h1.52
  text "BOTTOM ROW" at 161.29,24.765 h1.02
Mechanical 5:
  lines w0.127: 87.89,-94.513 87.89,-85.833 ; 126.998,-79.008 244.3,-79.008 ; 126.998,-72.183 244.3,-72.183 ; 126.998,-61.092 244.3,-61.092 ; 126.998,-56.827 244.3,-56.827 ; 126.998,-52.561 244.3,-52.561 ; 126.998,-48.295 244.3,-48.295 ; 150.373,-65.358 150.373,-44.03 ; 167.871,-85.833 167.871,-65.358 ; 208.069,-65.358 208.069,-44.03 ; 227.092,-65.358 227.092,-44.03 ; 244.3,-44.03 87.89,-44.03 ; 87.89,-85.833 87.89,-44.03 ; 87.89,-85.833 126.998,-85.833 ; 87.89,-85.833 244.3,-85.833 ; 87.89,-44.03 126.998,-44.03 ; 126.998,-85.833 126.998,-65.358 ; 126.998,-85.833 244.3,-85.833 ; 126.998,-85.833 126.998,-44.03 ; 126.998,-85.833 126.998,-44.03 ; 126.998,-65.358 244.3,-65.358 ; 126.998,-65.358 244.3,-65.358 ; 226.233,-85.833 226.233,-72.183 ; 226.233,-85.833 244.3,-85.833 ; 226.233,-85.833 226.233,-72.183 ; 226.233,-79.008 226.233,-72.183 ; 226.233,-79.008 244.3,-79.008 ; 226.233,-79.008 226.233,-72.183 ; 226.233,-72.183 244.3,-72.183 ; 226.233,-72.183 244.3,-72.183 ; 244.3,-85.833 244.3,-65.358 ; 244.3,-85.833 244.3,-72.183 ; 244.3,-79.008 244.3,-72.183
  lines w0.5: -42.69,-94.502 -42.69,115.498 244.31,115.498 244.31,-94.502 87.91,-94.502 -42.69,-94.502
  text "Radio / Oceanography / Laboratory" at 93.837,-58.62 h4
  text "Indice" at 131.059,-63.948 h1.76
  text "Modification" at 170.028,-63.948 h1.76
  text "Date" at 213.702,-63.948 h1.76
  text "Dessine par" at 229.256,-64.031 h1.5
  text "Edition" at 127.969,-69.96 h1.76
  text ":" at 147.907,-69.96 h1.76
  text "CARTE CRX-8-21" at 171.71,-70.602 h1.8
  text "Dessinateur" at 127.969,-75.971 h1.76
  text "Folio" at 227.108,-75.971 h1.8
  text ":" at 147.907,-75.992 h1.76
  text ":" at 235.577,-75.992 h1.76
  text "1/1" at 237.954,-76.367 h1.76
  text "RONVEL" at 150.975,-76.482 h1.95
  text ":" at 147.907,-82.585 h1.76
  text "Date" at 127.969,-82.636 h1.76
  text "Ind" at 227.108,-82.636 h1.95
  text "30-03-21" at 150.01,-83.602 h1.8
Mechanical7:
  text "PLAN DE CABLAGE" at 175.71,-77.102 h4
Mechanical9:
  text "PLAN DE PERCAGE" at 181.31,-77.002 h4
DrillDrawing:
  drawing of 612 lines, arcs and shapes, not listed
  text "EMPILAGE" at 27.979,-12.931 h2.5
  text "Layer" at -22.734,-17.943 h1.3
  text "Name" at -14.086,-17.943 h1.3
  text "Material" at 4.526,-17.943 h1.3
  text "Thickness" at 22.921,-17.943 h1.3
  text "Constant" at 36.767,-17.943 h1.3
  text "Board Layer Stack" at 48.881,-17.943 h1.3
  text "Board Layer Stack" at 72.907,-17.943 h1.3
  text "Board Layer Stack" at 96.934,-17.943 h1.3
  text "Board Layer Stack" at 120.96,-17.943 h1.3
  text "1" at -22.734,-20.543 h1.3
  text "TopOverlay" at -14.086,-20.543 h1.3
  text "2" at -22.734,-23.143 h1.3
  text "TopSolder" at -14.086,-23.143 h1.3
  text "Solder Resist" at 4.526,-23.143 h1.3
  text "0,020mm" at 22.921,-23.143 h1.3
  text "4" at 36.767,-23.143 h1.3
  text "3" at -22.734,-25.743 h1.3
  text "TopLayer" at -14.086,-25.743 h1.3
  text "Copper" at 4.526,-25.743 h1.3
  text "0,035mm" at 22.921,-25.743 h1.3
  text "MATIERE FR4 ( voir empilage) / CUIVRE 35 Microns 2 faces / TECHNO DOUBLE FACE / VERNIS SELECTIF VERT 2 FACES / SERIGRAPHIE BLANCHE FACE TOP / FINITION NiAu" at 157.794,-25.912 h1.52
  text "4" at -22.734,-28.343 h1.3
  text "Dielectric1" at -14.086,-28.343 h1.3
  text "FR-4" at 4.526,-28.343 h1.3
  text "1,465mm" at 22.921,-28.343 h1.3
  text "4,74" at 36.767,-28.343 h1.3
  text "5" at -22.734,-30.943 h1.3
  text "BottomLayer" at -14.086,-30.943 h1.3
  text "Copper" at 4.526,-30.943 h1.3
  text "0,035mm" at 22.921,-30.943 h1.3
  text "6" at -22.734,-33.543 h1.3
  text "BottomSolder" at -14.086,-33.543 h1.3
  text "Solder Resist" at 4.526,-33.543 h1.3
  text "0,020mm" at 22.921,-33.543 h1.3
  text "4" at 36.767,-33.543 h1.3
  text "7" at -22.734,-36.143 h1.3
  text "BottomOverlay" at -14.086,-36.143 h1.3
  text "IMPEDANCE / PISTES 1.064mm 50 ohms / PISTES .200mm 100 ohms" at 157.794,-37.452 h1.52
  text "Symbol" at -36.126,-43.719 h1.5
  text "Count" at -25.444,-43.719 h1.5
  text "Hole Size" at -11.61,-43.719 h1.5
  text "Plated" at 12.843,-43.719 h1.5
  text "Hole Type" at 23.525,-43.719 h1.5
  text "Drill Layer Pair" at 38.955,-43.719 h1.5
  text "Via/Pad" at 67.78,-43.719 h1.5
  text "1" at -25.444,-46.843 h1.25
  text "1,219mm (48,00mil)" at -11.61,-46.843 h1.25
  text "PTH" at 12.843,-46.843 h1.25
  text "Round" at 23.525,-46.843 h1.25
  text "TopLayer - BottomLayer" at 38.955,-46.843 h1.25
  text "Pad" at 67.78,-46.843 h1.25
  text "1" at -25.444,-49.967 h1.25
  text "1,651mm (65,00mil)" at -11.61,-49.967 h1.25
  text "PTH" at 12.843,-49.967 h1.25
  text "Round" at 23.525,-49.967 h1.25
  text "TopLayer - BottomLayer" at 38.955,-49.967 h1.25
  text "Pad" at 67.78,-49.967 h1.25
  text "3" at -25.444,-53.092 h1.25
  text "1,170mm (46,06mil)" at -11.61,-53.092 h1.25
  text "PTH" at 12.843,-53.092 h1.25
  text "Round" at 23.525,-53.092 h1.25
  text "TopLayer - BottomLayer" at 38.955,-53.092 h1.25
  text "Pad" at 67.78,-53.092 h1.25
  text "4" at -25.444,-56.216 h1.25
  text "0,406mm (16,00mil)" at -11.61,-56.216 h1.25
  text "PTH" at 12.843,-56.216 h1.25
  text "Round" at 23.525,-56.216 h1.25
  text "TopLayer - BottomLayer" at 38.955,-56.216 h1.25
  text "Pad" at 67.78,-56.216 h1.25
  text "5" at -25.444,-59.34 h1.25
  text "0,813mm (32,00mil)" at -11.61,-59.34 h1.25
  text "PTH" at 12.843,-59.34 h1.25
  text "Round" at 23.525,-59.34 h1.25
  text "TopLayer - BottomLayer" at 38.955,-59.34 h1.25
  text "Pad" at 67.78,-59.34 h1.25
  text "10" at -25.444,-62.464 h1.25
  text "0,711mm (28,00mil)" at -11.61,-62.464 h1.25
  text "PTH" at 12.843,-62.464 h1.25
  text "Round" at 23.525,-62.464 h1.25
  text "TopLayer - BottomLayer" at 38.955,-62.464 h1.25
  text "Via" at 67.78,-62.464 h1.25
  text "13" at -25.444,-65.588 h1.25
  text "3,300mm (129,92mil)" at -11.61,-65.588 h1.25
  text "PTH" at 12.843,-65.588 h1.25
  text "Round" at 23.525,-65.588 h1.25
  text "TopLayer - BottomLayer" at 38.955,-65.588 h1.25
  text "Pad" at 67.78,-65.588 h1.25
  text "15" at -25.444,-68.712 h1.25
  text "1,168mm (46,00mil)" at -11.61,-68.712 h1.25
  text "PTH" at 12.843,-68.712 h1.25
  text "Round" at 23.525,-68.712 h1.25
  text "TopLayer - BottomLayer" at 38.955,-68.712 h1.25
  text "Pad" at 67.78,-68.712 h1.25
  text "16" at -25.444,-71.836 h1.25
  text "1,702mm (67,00mil)" at -11.61,-71.836 h1.25
  text "PTH" at 12.843,-71.836 h1.25
  text "Round" at 23.525,-71.836 h1.25
  text "TopLayer - BottomLayer" at 38.955,-71.836 h1.25
  text "Pad" at 67.78,-71.836 h1.25
  text "67" at -25.444,-74.961 h1.25
  text "0,965mm (38,00mil)" at -11.61,-74.961 h1.25
  text "PTH" at 12.843,-74.961 h1.25
  text "Round" at 23.525,-74.961 h1.25
  text "TopLayer - BottomLayer" at 38.955,-74.961 h1.25
  text "Pad" at 67.78,-74.961 h1.25
  text "78" at -25.444,-78.085 h1.25
  text "0,508mm (20,00mil)" at -11.61,-78.085 h1.25
  text "PTH" at 12.843,-78.085 h1.25
  text "Round" at 23.525,-78.085 h1.25
  text "TopLayer - BottomLayer" at 38.955,-78.085 h1.25
  text "Via" at 67.78,-78.085 h1.25
  text "4234" at -25.444,-81.209 h1.25
  text "0,300mm (11,81mil)" at -11.61,-81.209 h1.25
  text "PTH" at 12.843,-81.209 h1.25
  text "Round" at 23.525,-81.209 h1.25
  text "TopLayer - BottomLayer" at 38.955,-81.209 h1.25
  text "Via" at 67.78,-81.209 h1.25
  text "4447 Total" at -25.444,-84.333 h1.25

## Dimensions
2.54,101.6 to 2.54,0 on DrillDrawing
160.02,2.54 to 0,2.54 on DrillDrawing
